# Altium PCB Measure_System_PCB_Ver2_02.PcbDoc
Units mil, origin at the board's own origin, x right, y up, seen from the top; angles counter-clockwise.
Board outline 2800 x 2200 mil, 2 copper layers (Top Layer, Bottom Layer); 51 components, 32 nets, 144 pads, 5 vias.
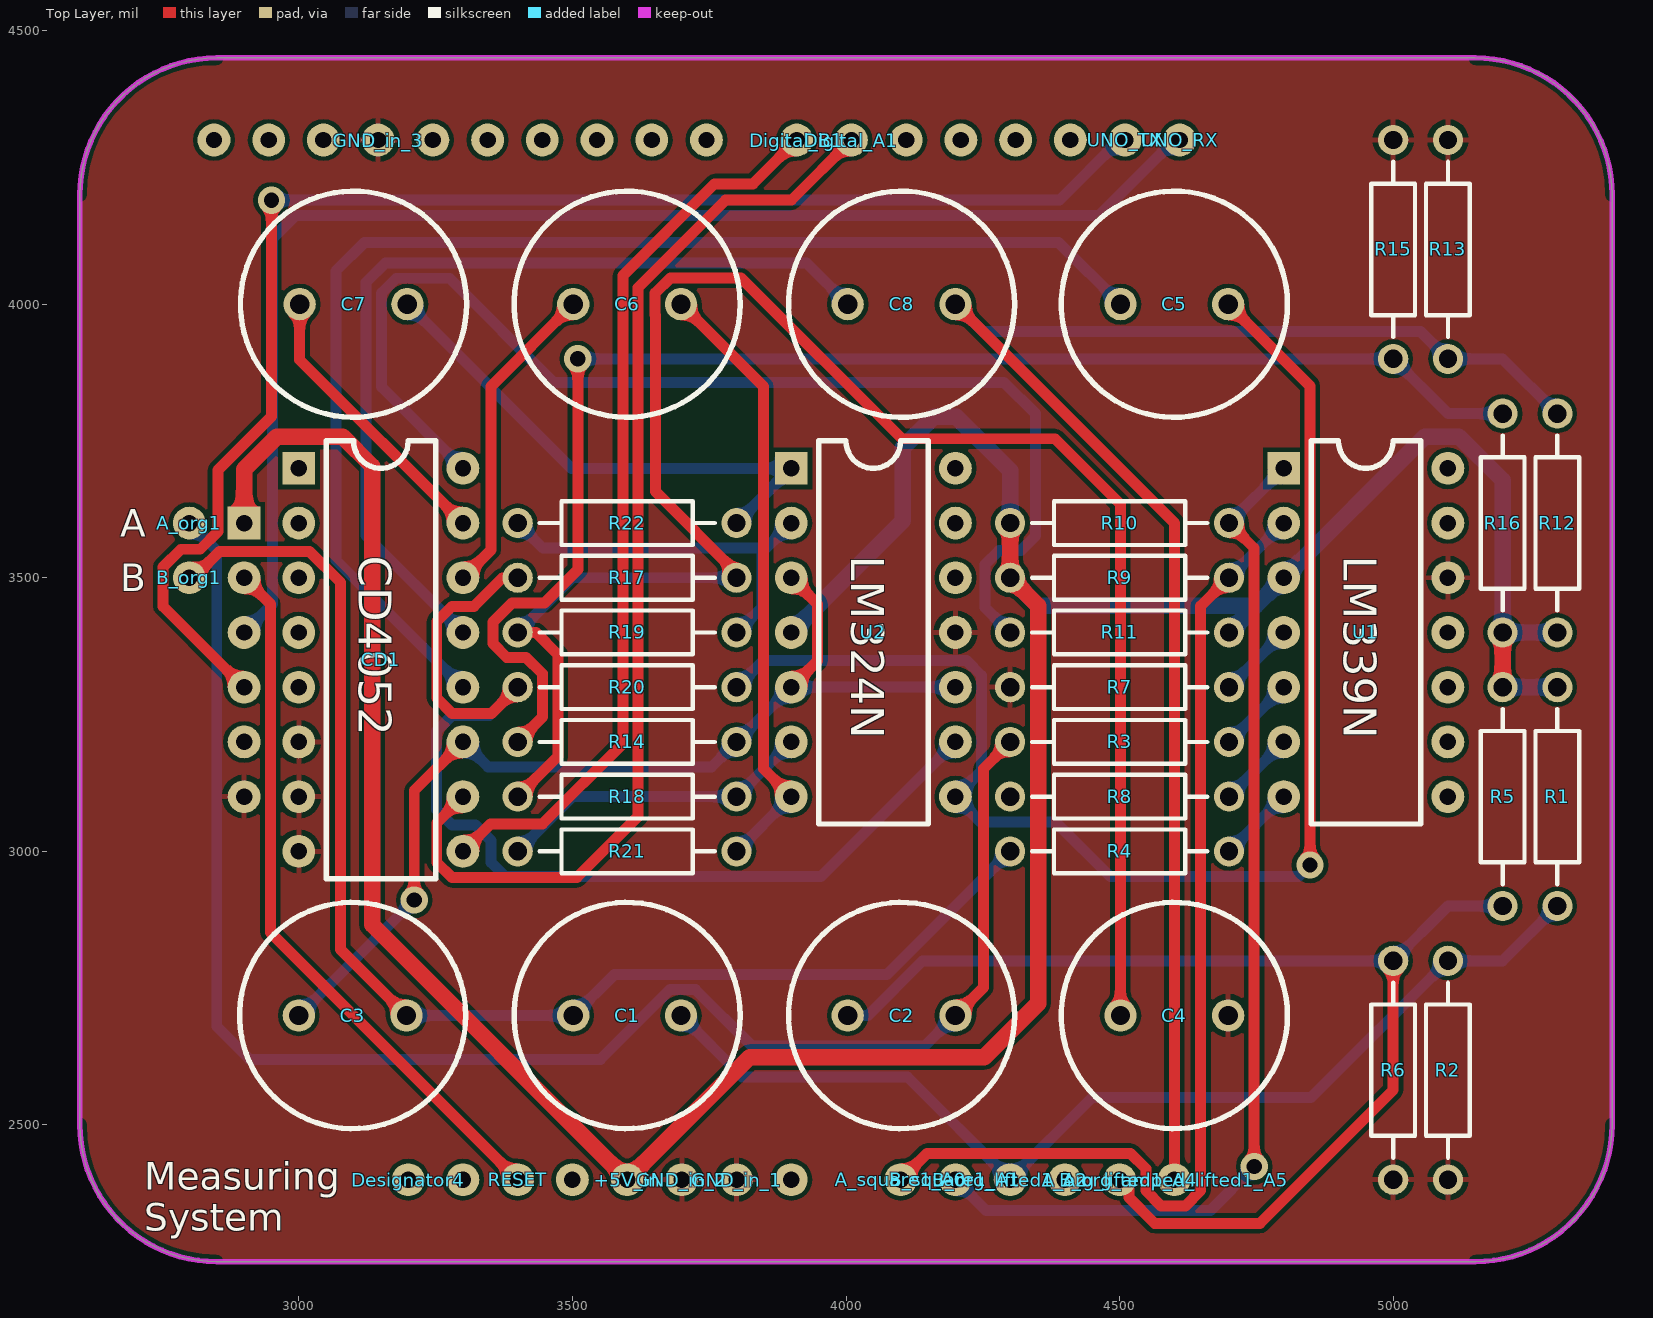
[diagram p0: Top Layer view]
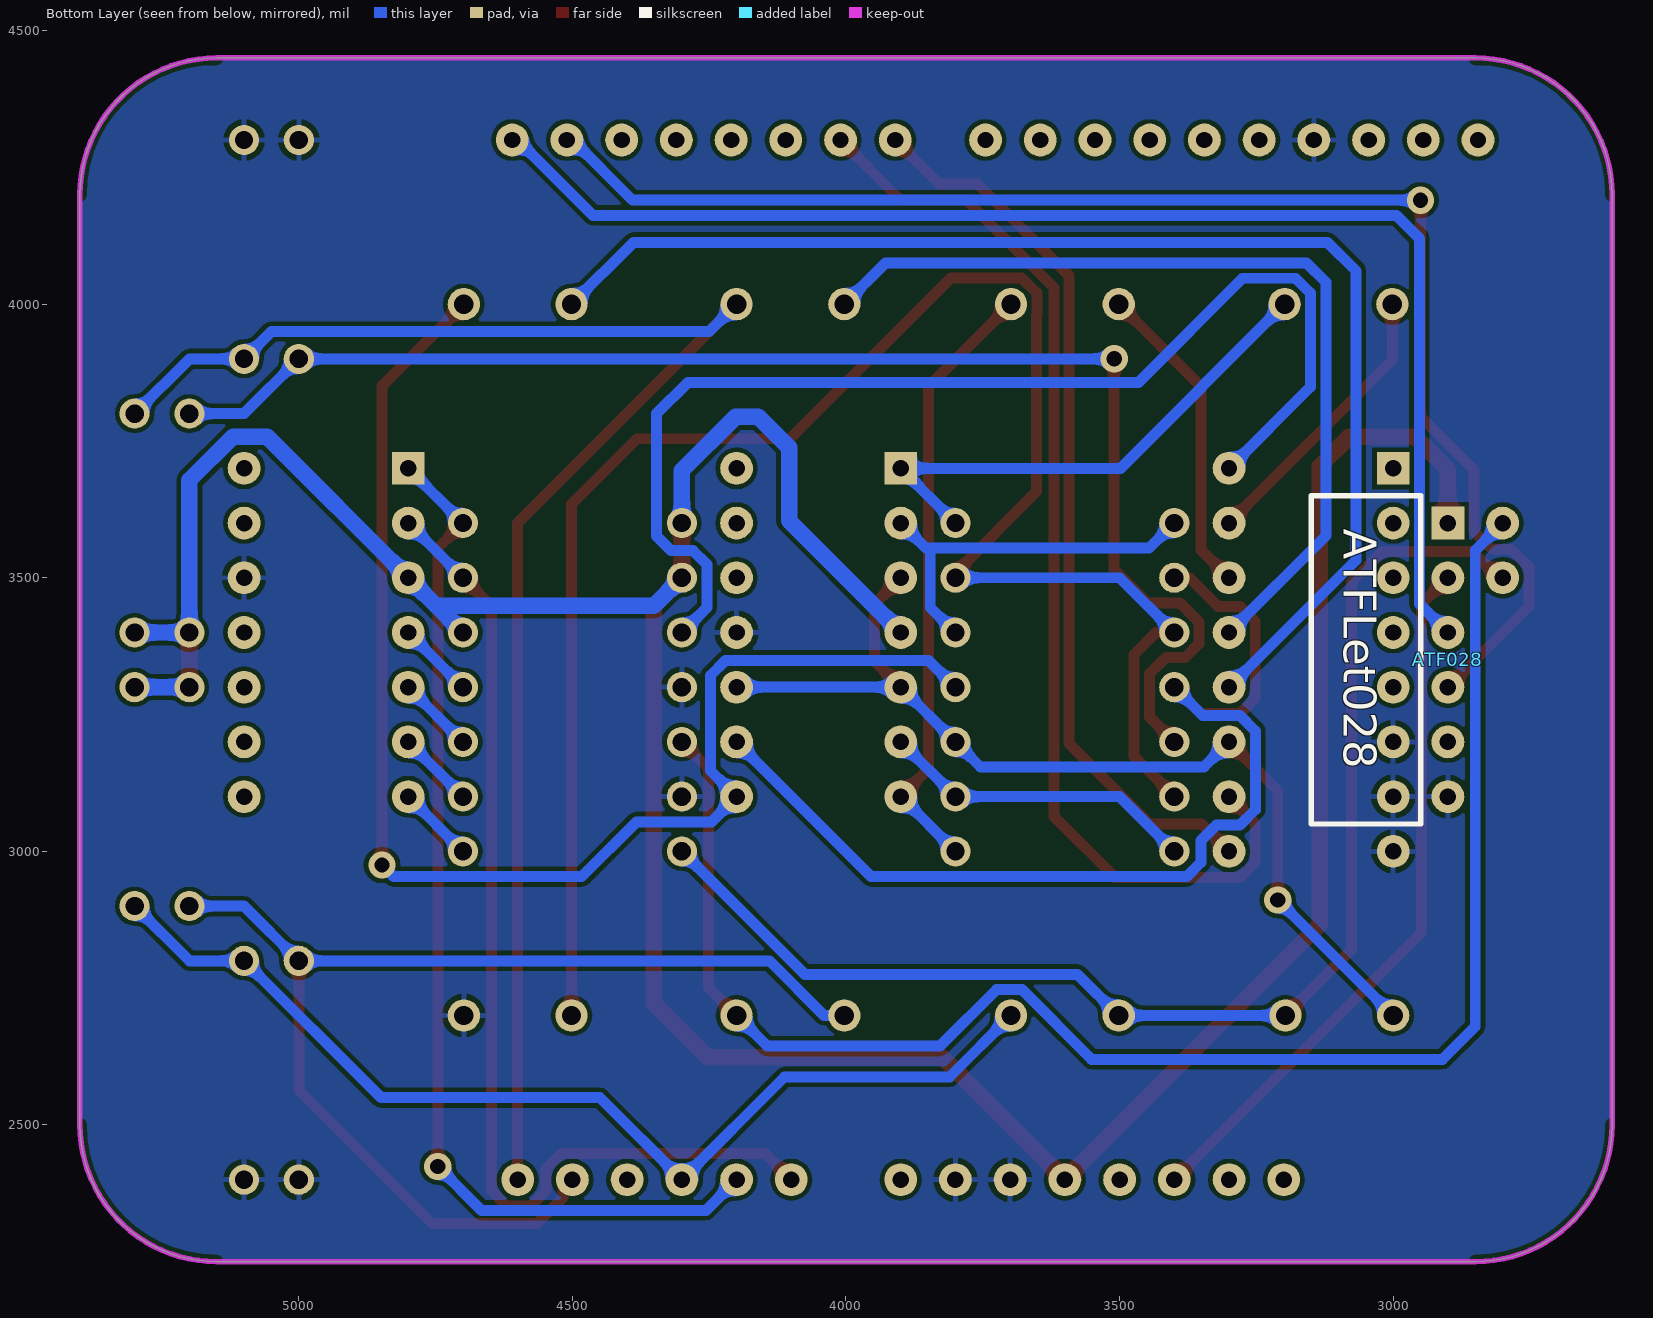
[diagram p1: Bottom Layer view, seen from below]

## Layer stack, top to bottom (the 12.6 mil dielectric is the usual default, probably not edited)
Top Solder: solder mask 0.4, Solder Resist, Dk 3.5
Top Layer: signal copper 1.4
Dielectric 1: dielectric 12.6, FR-4, Dk 4.8
Bottom Layer: signal copper 1.4
Bottom Solder: solder mask 0.4, Solder Resist, Dk 3.5

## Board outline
2600,2500 ccw(c2850,2500) 2850,2250 5150,2250 ccw(c5150,2500) 5400,2500 5400,4200 ccw(c5150,4200) 5150,4450 2850,4450 ccw(c2850,4200) 2600,4200

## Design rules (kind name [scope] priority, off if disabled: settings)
Clearance [All] p1: gap=7.87 ignorepadtopadclearanceinfootprint=FALSE
PolygonConnect [All] p1: connectstyle=Relief reliefconductorwidth=10 reliefentries=4 polygonreliefangle="90 Angle" airgapwidth=10
RoutingVias [All] p1: holewidth=28 width=50 viastyle="Through Hole" minholewidth=28 minwidth=50 maxholewidth=28 maxwidth=50
SolderMaskExpansion [All] p1: expansion=4 istentingtop=FALSE
Width Width_2 [InNet('GND')] p1: maxlimit=50 minlimit=10 preferedwidth=30 minimp=50.000000 maximp=50.000000 favimp=50.000000
Width Width_1 [InNet('+5')] p2: maxlimit=50 minlimit=10 preferedwidth=30 minimp=50.000000 maximp=50.000000 favimp=50.000000
Width [All] p3: maxlimit=50 minlimit=10 preferedwidth=20
30 further rules are at their usual default settings.

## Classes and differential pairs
component class Part_Square: C1 C2 R1 R2 R3 R4 R5 R6 R7 R8 R9 R10 U1
component class Part_PGA: C3 C4 C5 C6 C7 C8 CD1 R11 R12 R13 R14 R15 R16 R17 R18 R19 R20 R21 R22 U2
component class Measure_System_Main: +5V_in A_org1 A_org_lifted1_A4 A_square1_A0 ATF028 B_org1 B_org_amped_lifted1_A5 B_org_lifted1_A2 B_square1_A1 Digital_A1 Digital_B1 GND_in_1 GND_in_2 GND_in_3 RESET UNO_RX UNO_TX

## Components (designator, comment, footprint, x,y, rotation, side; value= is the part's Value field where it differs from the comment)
+5V_in "Hole" Hole 3600,2400 r90 top
A_org1 "Hole" Hole 2800,3600 r90 top
A_org_lifted1_A4 "Hole" Hole 4500,2400 r90 top
A_square1_A0 "Hole" Hole 4100,2400 r90 top
ATF028 "ATFLet028" ATFLet028 2900,3600 r180 bottom
B_org1 "Hole" Hole 2800,3500 r90 top
B_org_amped_lifted1_A5 "Hole" Hole 4600,2400 r90 top
B_org_lifted1_A2 "Hole" Hole 4300,2400 r90 top
B_square1_A1 "Hole" Hole 4200,2400 r90 top
C1 "Cap Pol1" RB5-10.5 3600,2700 r0 top value=10u
C2 "Cap Pol1" RB5-10.5 4101.58,2700 r180 top value=10u
C3 "Cap Pol1" RB5-10.5 3098.43,2700 r180 top value=10u
C4 "Cap Pol1" RB5-10.5 4600,2700 r180 top value=10u
C5 "Cap Pol1" RB5-10.5 4600,4000 r180 top value=10u
C6 "Cap Pol1" RB5-10.5 3600,4000 r180 top value=10u
C7 "Cap Pol1" RB5-10.5 3100,4000 r180 top value=10u
C8 "Cap Pol1" RB5-10.5 4101.57,4000 r0 top value=10u
CD1 "CD4052" CD4052 3000,3700 r0 top
Designator4 "Comment" Hole 3200,2400 r0 top
Digital_A1 "Hole" Hole 4010,4300 r90 top
Digital_B1 "Hole" Hole 3910,4300 r90 top
GND_in_1 "Hole" Hole 3800,2400 r90 top
GND_in_2 "Hole" Hole 3700,2400 r90 top
GND_in_3 "Hole" Hole 3145,4300 r90 top
R1 "Res2" AXIAL-0.4 5300,3100 r90 top value=100k
R2 "Res2" AXIAL-0.4 5100,2600 r90 top value=100k
R3 "Res2" AXIAL-0.4 4500,3200 r180 top value=1k
R4 "Res2" AXIAL-0.4 4500,3000 r180 top value=1k
R5 "Res2" AXIAL-0.4 5200,3100 r90 top value=100k
R6 "Res2" AXIAL-0.4 5000,2600 r90 top value=100k
R7 "Res2" AXIAL-0.4 4500,3300 r0 top value=10k
R8 "Res2" AXIAL-0.4 4500,3100 r180 top value=10k
R9 "Res2" AXIAL-0.4 4500,3500 r0 top value=10k
R10 "Res2" AXIAL-0.4 4500,3600 r180 top value=10k
R11 "Res2" AXIAL-0.4 4500,3400 r0 top value=200
R12 "Res2" AXIAL-0.4 5300,3600 r270 top value=100k
R13 "Res2" AXIAL-0.4 5100,4100 r270 top value=100k
R14 "Res2" AXIAL-0.4 3600,3200 r0 top value=100k
R15 "Res2" AXIAL-0.4 5000,4100 r270 top value=100k
R16 "Res2" AXIAL-0.4 5200,3600 r90 top value=100k
R17 "Res2" AXIAL-0.4 3600,3500 r180 top value=50k
R18 "Res2" AXIAL-0.4 3600,3100 r0 top value=24k
R19 "Res2" AXIAL-0.4 3600,3400 r0 top value=12k
R20 "Res2" AXIAL-0.4 3600,3300 r0 top value=100k
R21 "Res2" AXIAL-0.4 3600,3000 r0 top value=100k
R22 "Res2" AXIAL-0.4 3600,3600 r0 top value=100k
RESET "Hole" Hole 3400,2400 r90 top
U1 "LM339N" LM339N 4800,3700 r0 top
U2 "LM324N" LM324N 3900,3700 r0 top
UNO_RX "Hole" Hole 4610,4300 r90 top
UNO_TX "Hole" Hole 4510,4300 r90 top

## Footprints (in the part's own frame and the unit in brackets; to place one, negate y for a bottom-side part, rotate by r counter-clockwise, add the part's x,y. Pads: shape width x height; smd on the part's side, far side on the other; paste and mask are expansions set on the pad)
ATFLet028 [mil]
  rect 60x60 hole 30: 1(0,0)
  round 60 hole 30 mask+4: 2(0,-100) 3(0,-200) 4(0,-300) 5(0,-400) 6(0,-500)
  silkscreen extent -250,-550 -50,50
AXIAL-0.4 [mm] "Axial Device, Thru-Hole; 2 Leads; 0.4 in Pin Spacing"
  round 1.4 hole 0.85: 1(-5.08,0) 2(5.08,0)
  silkscreen extent -4.06,-1.02 4.06,1.02
CD4052 [mil]
  rect 60x60 hole 30: 1(0,0)
  round 60 hole 30 mask+4: 2(0,-100) 3(0,-200) 4(0,-300) 5(0,-400) 6(0,-500) 7(0,-600) 8(0,-700) 9(300,-700) 10(300,-600) 11(300,-500) 12(300,-400) 13(300,-300) 14(300,-200) 15(300,-100) 16(300,0)
  silkscreen extent 50,-750 250,50
Hole [mil]
  round 60 hole 30 mask+4: 1(0,0)
LM324N [mil]
  rect 60x60 hole 30: 1(0,0)
  round 60 hole 30 mask+4: 2(0,-100) 3(0,-200) 4(0,-300) 5(0,-400) 6(0,-500) 7(0,-600) 8(300,-600) 9(300,-500) 10(300,-400) 11(300,-300) 12(300,-200) 13(300,-100) 14(300,0)
  silkscreen extent 50,-650 250,50
LM339N [mil]
  rect 60x60 hole 30: 1(0,0)
  round 60 hole 30 mask+4: 2(0,-100) 3(0,-200) 4(0,-300) 5(0,-400) 6(0,-500) 7(0,-600) 8(300,-600) 9(300,-500) 10(300,-400) 11(300,-300) 12(300,-200) 13(300,-100) 14(300,0)
  silkscreen extent 50,-650 250,50
RB5-10.5 [mm] "Capacitor (Radial); 2 Leads"
  round 1.5 hole 0.9: 1(-2.5,0) 2(2.5,0)
  silkscreen extent -5.25,-5.25 5.25,5.25

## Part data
C1 C2 C3 C4 C5 C6 C7 C8: "Polarized Capacitor (Radial)"
R1 R2 R3 R4 R5 R6 R7 R8 R9 R10 R11 R12 R13 R14 R15 R16 R17 R18 R19 R20 R21 R22: "Resistor"

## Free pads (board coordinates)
  round 60 hole 30 mask+4: 5(4400,2400) 7(3900,2400) 8(3500,2400) 10(3300,2400) 11(4410,4300) 12(4310,4300) 13(4210,4300) 14(4110,4300) 15(3745,4300) 17(3545,4300) 18(3445,4300) 19(3345,4300) 20(3245,4300) 22(3045,4300) 23(2945,4300) 24(2845,4300) 26(3645,4300)

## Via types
v1: diameter 50, hole 28, Top Layer to Bottom Layer, 5 vias

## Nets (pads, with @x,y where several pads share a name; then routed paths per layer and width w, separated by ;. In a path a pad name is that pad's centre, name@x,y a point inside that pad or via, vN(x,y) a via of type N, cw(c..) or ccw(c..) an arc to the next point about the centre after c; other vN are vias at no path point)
+5: +5V_in.1 ATF028.1 R1.2 R5.2 R9.1 R10.2 R11.2 R12.2 R16.1 U1.3 U2.4 | length 6167.6
  Top Layer w30: ATF028.1 2900,3698 2960,3758 3080,3758 3134,3704 3134,2866 +5V_in.1 3824,2624 4253,2624 4351,2722 4351,3449 R9.1 R10.2 ; R5.2 R16.1
  Bottom Layer w30: U2.4 4104,3604 4104,3738 4160,3794 4202,3794 4300,3696 R10.2 ; R9.1 4351,3449 4749,3449 ; R11.2 4749,3449 ; R5.2 R1.2 ; R12.2 R16.1 5200,3678 5120,3758 5058,3758 U1.3 4749,3449
B_org: B_org1.1 C1.1 C3.1 R4.2 | length 2388.3
  Top Layer w20: B_org1.1 2807.12,3500 2855,3547.87 3019.83,3547.87 3076,3491.7 3076,2820.85 C3.1
  Bottom Layer w20: C3.1 C1.1 3576.85,2775.28 4075.28,2775.28 R4.2
B_org_amp_1: C3.2 CD1.11 R14.2 U2.3 U2.5 U2.10 | length 1843.1
  Top Layer w20: v1(3211,2911) 3211,3111 CD1.11 ; U2.5 3948,3348 3948,3452 U2.3
  Bottom Layer w20: C3.2 v1(3211,2911) ; CD1.11 3345.43,3154.57 3754.57,3154.57 R14.2 U2.5 U2.10
B_org_amp_2.5: C5.2 CD1.12 | length 2359
  Bottom Layer w20: CD1.12 3068,3532 3068,4061 3120,4113 4388.57,4113 C5.2
B_org_amp_5: C6.2 CD1.14 | length 583.5
  Top Layer w20: CD1.14 3351,3551 3351,3849.43 C6.2
B_org_amp_10: C7.2 CD1.15 | length 523.6
  Top Layer w20: C7.2 3001.58,3898.42 CD1.15
B_org_amped: C8.1 CD1.13 | length 1639
  Bottom Layer w20: CD1.13 3123.15,3576.85 3123.15,4040 3158.43,4075.28 3927.87,4075.28 C8.1
Digital_A: CD1.10 Digital_A1.1 | length 2033.6
  Top Layer w20: CD1.10 3252.13,3052.13 3252.13,2979.87 3280,2952 3508,2952 3620,3064 3620,4030 3780,4190 3900,4190 Digital_A1.1
Digital_B: CD1.9 Digital_B1.1 | length 1649.3
  Top Layer w20: CD1.9 3350,3050 3445,3050 3592.13,3197.13 3592.13,4052.13 3760,4220 3830,4220 Digital_B1.1
GND: ATF028.6 C4.1 CD1.6 CD1.7 CD1.8 GND_in_1.1 GND_in_2.1 GND_in_3.1 R2.1 R6.1 R7.1 R8.2 R13.1 R15.1 U1.12 U2.11
NetA_org1_1: A_org1.1 C2.1 R3.2 | length 2975.8
  Top Layer w20: C2.1 4251,2751 4251,3151 R3.2
  Bottom Layer w20: A_org1.1 2850,3550 2850,2680 2910,2620 3551,2620 3678.4,2747.4 3724.6,2747.4 3828,2644 4144,2644 C2.1
NetA_org_lifted1_A4_1: A_org_lifted1_A4.1 C2.2 R5.1 R6.2 | length 2159.2
  Top Layer w20: A_org_lifted1_A4.1 4517.09,2382.91 4517.09,2367.16 4564.25,2320 4756.2,2320 5000,2563.8 R6.2
  Bottom Layer w20: C2.2 4040,2700 4140,2800 R6.2 5100,2900 R5.1
NetA_square1_A0_1: A_square1_A0.1 R9.2 U1.2 | length 1925.5
  Top Layer w20: A_square1_A0.1 4148,2448 4520,2448 4548,2420 4548,2380 4575.87,2352.13 4620.13,2352.13 4648,2380 4648,3448 R9.2
  Bottom Layer w20: R9.2 U1.2
NetATF028_2: ATF028.2 RESET.1 | length 1307.1
  Top Layer w20: ATF028.2 2948,3452 2948,2852 RESET.1
NetATF028_3: ATF028.3 UNO_RX.1 | length 2464.1
  Bottom Layer w20: ATF028.3 2952,3452 2952,4120 2994.13,4162.13 4462.13,4162.13 UNO_RX.1@4600,4300
NetATF028_4: ATF028.4 UNO_TX.1 | length 2649.5
  Top Layer w20: ATF028.4 2752.13,3447.87 2752.13,3519.83 2784.42,3552.13 2819.83,3552.13 2852.13,3584.42 2852.13,3696.62 2950,3794.49 v1(2950,4190)
  Bottom Layer w20: v1(2950,4190) 4390,4190 UNO_TX.1@4500,4300
NetB_org_amped_lifted1_A5_1: B_org_amped_lifted1_A5.1 C8.2 R12.1 R13.2 | length 2948.5
  Top Layer w20: C8.2 4600,3600 B_org_amped_lifted1_A5.1
  Bottom Layer w20: C8.2 4250,3950 5050,3950 R13.2 5200,3900 R12.1
NetB_org_lifted1_A2_1: B_org_lifted1_A2.1 C1.2 R1.1 R2.2 | length 1932.9
  Bottom Layer w20: C1.2 3810.43,2588 4112,2588 B_org_lifted1_A2.1 4450,2550 4850,2550 R2.2 5200,2800 R1.1
NetB_square1_A1_1: B_square1_A1.1 R10.1 U1.1 | length 1938.8
  Top Layer w20: R10.1 4746,3554 v1(4746,2424)
  Bottom Layer w20: B_square1_A1.1 4256,2344 4666,2344 v1(4746,2424) ; R10.1 U1.1
NetC4_2: C4.2 R17.1 R18.1 R19.1 | length 3371.3
  Top Layer w20: R18.1 3473.31,3173.31 3473.31,3360 3433.31,3400 R19.1 ; R17.1 3800,3509.03 3651.61,3657.43 3651.61,3979.78 3651.02,3980.37 3651.02,4020.02 3679,4048 3808,4048 4102,3754 4382,3754 4501.57,3634.43 C4.2
  Bottom Layer w20: R19.1 3500,3500 R17.1
NetC5_1: C5.1 R20.2 U2.8 | length 2524.9
  Top Layer w20: C5.1 4848,3850.43 v1(4848,2975)
  Bottom Layer w20: R20.2 3849,3349 4220,3349 4248,3321 4248,3148 U2.8 4246,3054 4383,3054 4483,2954 4827,2954 v1(4848,2975)
NetC6_1: C6.1 R21.2 U2.7 | length 1124.9
  Top Layer w20: C6.1 3849,3849.43 3849,3151 U2.7
  Bottom Layer w20: R21.2 U2.7
NetC7_1: C7.1 R22.2 U2.1 | length 967.3
  Bottom Layer w20: C7.1 3498.43,3700 U2.1 R22.2
NetCD1_16: CD1.16 R11.1 | length 2171.1
  Bottom Layer w20: CD1.16 3151.02,3848.98 3151.02,4020 3178.43,4047.4 3275.4,4047.4 3465.8,3857 4289,3857 4346,3800 4346,3576 4320,3550 4280,3550 4254,3524 4254,3446 R11.1
NetR3_1: R3.1 U1.5 | length 141.4
  Bottom Layer w20: R3.1 U1.5
NetR4_1: R4.1 U1.7 | length 141.4
  Bottom Layer w20: R4.1 U1.7
NetR7_2: R7.2 U1.4 | length 141.4
  Bottom Layer w20: R7.2 U1.4
NetR8_1: R8.1 U1.6 | length 141.4
  Bottom Layer w20: R8.1 U1.6
NetR14_1: R14.1 R15.2 R16.2 | length 2607.7
  Top Layer w20: R14.1 3445.43,3245.43 3445.43,3324.57 3415.43,3354.57 3380,3354.57 3354.57,3380 3354.57,3418.82 3389.75,3454 3449,3454 3510,3515 v1(3510,3900)
  Bottom Layer w20: v1(3510,3900) R15.2 5100,3800 R16.2
NetR17_2: R17.2 R20.1 U2.9 | length 1949.3
  Top Layer w20: R20.1 3352.13,3252.13 3280,3252.13 3252.13,3280 3252.13,3420 3280,3447.87 3320,3447.87 3372.13,3500 R17.2
  Bottom Layer w20: R20.1 3348,3248 3280,3248 3252,3220 3252,3076 3280,3048 3323,3048 3351,3020 3351,2980 3377,2954 3954,2954 U2.9
NetR18_2: R18.2 R21.1 U2.6 | length 582.8
  Bottom Layer w20: R21.1 3500,3100 R18.2 U2.6
NetR19_2: R19.2 R22.1 U2.2 | length 711.2
  Bottom Layer w20: R22.1 3446,3554 3846,3554 ; R19.2 3846,3446 3846,3554 ; U2.2 3854,3554 3846,3554
pads on no net: ATF028.5 CD1.1 CD1.2 CD1.3 CD1.4 CD1.5 Designator4.1 U1.8 U1.9 U1.10 U1.11 U1.13 U1.14 U2.12 U2.13 U2.14

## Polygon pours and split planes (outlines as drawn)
GND on Bottom Layer "NONET_L-01_P-001" (solid, remove dead copper, pour order 15): 2600,2500 ccw(c2850,2500) 2850,2250 5150,2250 ccw(c5150,2500) 5400,2500 5400,4200 ccw(c5150,4200) 5150,4450 2850,4450 ccw(c2850,4200) 2600,4200
GND on Top Layer "NONET_L-01_P-001" (solid, remove dead copper, pour order 12): 2600,4200 cw(c2850,4200) 2850,4450 5150,4450 cw(c5150,4200) 5400,4200 5400,2500 cw(c5150,2500) 5150,2250 2850,2250 cw(c2850,2500) 2600,2500

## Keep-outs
Keep-Out Layer:
  the board outline again, w10

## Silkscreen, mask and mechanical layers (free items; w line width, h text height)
Top Overlay:
  text "A" at 2673.34,3575.01 h50
  text "B" at 2673.34,3475.01 h50
  text "Measuring / System" at 2717.57,2306.36 h50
